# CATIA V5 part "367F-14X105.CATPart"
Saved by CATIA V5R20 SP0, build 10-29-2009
Part number: 367F-14X105
Definition: NONE
Nomenclature: 367F-14X105
Source: Unknown
Description: 367F-14X105
Bounding box of the stored display mesh (mm): x 0 to 105, y -14 to 14, z -14 to 14
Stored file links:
  C:\Users\Utente\Desktop\IO LAVORO\3D X SITO CF\X SITO\PLASTICA\3D files 367\367F-14X105.CATPart
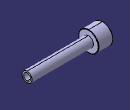
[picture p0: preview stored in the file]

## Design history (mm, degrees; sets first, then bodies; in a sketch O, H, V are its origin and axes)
Body1 "367F-14X105" (main body)
  Solid1: solid without history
